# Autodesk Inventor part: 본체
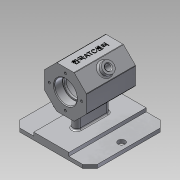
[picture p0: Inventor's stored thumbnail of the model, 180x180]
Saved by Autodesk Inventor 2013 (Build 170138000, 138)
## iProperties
Created: 2018-06
Part Number: 본체
Material: 알루미늄 6061
Document SubType Name: Modeling
Designer: default
Density: 2.71 g/cm^3
Mass: 553.88 g
Surface Area: 602.123 cm^2
Volume: 204.384 cm^3
Author: default
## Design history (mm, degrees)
sketch "스케치1"
  geometry: L1 (-55, -55)-(55, -55); L2 (55, -55)-(55, 55); L3 (55, 55)-(-55, 55); L4 (-55, 55)-(-55, -55); L5 (-55, -55)-(55, 55); L6 (55, -55)-(-55, 55); 1 further point
  constraints: 12 end point, 2 midpoint, 2 parallel, 2 perpendicular, 1 horizontal
  dimensions: "d0" = 110 distance of L2.end L3.end
extrude "돌출1" new body sketch "스케치1" distance "d2" = 5; taper "d3" = 0 deg
chamfer "모따기1" distance "d4" = 10; stored, may be unused: second distance "d5" = 2, angle "d6" = 45 deg
sketch "스케치2"
  geometry: L1 (55, -45)-(55, 45) reference; L2 (45, 55)-(-45, 55) reference; L3 (-55, -25)-(55, -25); L4 (55, -25)-(55, 25); L5 (55, 25)-(-55, 25); L6 (-55, 25)-(-55, -25); L7 (-55, -25)-(55, 25); L8 (55, -25)-(-55, 25); 1 further point
  constraints: 12 end point, 2 midpoint, 2 parallel, 1 horizontal, 1 perpendicular, 1 point on line
  dimensions: "d7" = 30 distance between parallel lines of L2 L5
extrude "돌출2" join sketch "스케치2" distance "d8" = 5; taper "d9" = 0 deg
sketch "스케치3" dims "d10" = 60
  geometry: L1 (25, 10)-(25, 5) reference; L2 (25, 5)-(55, 5) reference; L3 (55, 5)-(55, 0) reference; L4 (55, 0)-(-55, 0) reference; L5 (-55, 0)-(-55, 5) reference; L6 (-55, 5)-(-25, 5) reference; L7 (-25, 5)-(-25, 10) reference; L8 (-25, 10)-(25, 10) reference; L9 (12.426, 92)-(30, 74.426); L10 (30, 74.426)-(30, 49.574); L11 (30, 49.574)-(12.426, 32); L12 (12.426, 32)-(-12.426, 32); L13 (-12.426, 32)-(-30, 49.574); L14 (-30, 49.574)-(-30, 74.426); L15 (-30, 74.426)-(-12.426, 92); L16 (-12.426, 92)-(12.426, 92); 4 further points
  constraints: 16 end point, 2 vertical alignment, 1 coincident, 1 midpoint, 1 parallel, 19 other
  dimensions: "d12" = 62 vertical distance of L4.end point (0, 62)
extrude "돌출3" join sketch "스케치3" stored distance "d13" = 70; taper "d14" = 0 deg
sketch "스케치4"
  geometry: L1 (-55, 10)-(55, 10) reference; L2 (55, 10)-(55, 0) reference; L3 (55, 0)-(-55, 0) reference; L4 (-55, 0)-(-55, 10) reference; L5 (35, 92)-(35, 32) reference; L6 (35, 32)-(-35, 32) reference; L7 (-35, 32)-(-35, 92) reference; L8 (-35, 92)-(35, 92) reference; L9 (-35, 62)-(35, 62); L10 (35, 78)-(23, 78); L11 (23, 78)-(23, 76); L12 (23, 76)-(20, 76); L13 (20, 76)-(20, 87); L14 (20, 87)-(-20, 87); L15 (-20, 87)-(-20, 76); L16 (-20, 76)-(-23, 76); L17 (-23, 76)-(-23, 78); L18 (-23, 78)-(-35, 78); 3 further points
  constraints: 20 end point, 7 parallel, 4 midpoint, 2 horizontal alignment, 2 perpendicular, 2 point on line, 1 vertical alignment
  dimensions: "d15" = 50 diameter of L14 L9; "d17" = 28 diameter of L15.end L9; "d18" = 32 diameter of L17.end L9; "d19" = 12 distance of L17.end L18.end; "d20" = 40 distance of L13.end L14.end; "d21" = 12 distance of L10.start L10.end
revolve "회전1" sketch "스케치4" stored, may be unused: angle "d22" = 90 deg
sketch "스케치5"
  geometry: C1 r 16 at (-62, 0) reference; 2 further points
  constraints: 1 vertical alignment
  dimensions: "d23" = 23 distance of C1.centre point (-62, 23)
hole "구멍1" sketch "스케치5" at (-62, 23) diameter "d24" = 3.242; stored, may be unused: countersink angle "d28" = 90 deg, drill point angle "d30" = 118 deg; dims "d25" = 8, "d26" = 4, "d27" = 2, "d29" = 10
sketch "스케치6"
  geometry: L1 (-19, -5)-(19, -5); L2 (24, 0)-(24, 0); L3 (19, 5)-(-19, 5); L4 (-24, 0)-(-24, 0); L5 (-24, -5)-(24, 5); L6 (24, -5)-(-24, 5); A1 r 5 centre (-19, 0) between (-19, 5) and (-24, 0); A2 r 5 centre (-19, 0) between (-24, 0) and (-19, -5); A3 r 5 centre (19, 0) between (19, -5) and (24, 0); A4 r 5 centre (19, 0) between (24, 0) and (19, 5); 1 further point
  constraints: 12 end point, 8 point on circle, 8 point on line, 8 tangent, 4 centre point, 3 equal radius, 2 midpoint, 2 parallel, 1 coincident, 1 horizontal, 1 perpendicular
  dimensions: "d34" = 5 radius of A1; "d35" = 38 distance of A3.centre A1.centre
extrude "돌출4" join sketch "스케치6" stored distance "d36" = 70; taper "d37" = 0 deg
sketch "스케치7"
  geometry: L1 (-45, -55)-(45, -55) reference; 2 further points
  constraints: 1 vertical alignment
  dimensions: "d38" = 10 distance from line of L1 point (0, -45)
hole "구멍2" sketch "스케치7" at (0, -45) diameter "d39" = 10; stored, may be unused: countersink angle "d43" = 90 deg, drill point angle "d45" = 118 deg; dims "d40" = 8, "d41" = 4, "d42" = 2, "d44" = 10
node "작업 평면1"
sketch "스케치8"
  geometry: L1 (70, 0)-(0, 0) reference; L2 (70, 24.853)-(70, 0) reference; L3 (70, 24.853)-(0, 24.853) reference; L4 (0, 0)-(0, 24.853) reference; C1 r 8 at (35, 12.426); 2 further points
  constraints: 1 centre point, 1 horizontal alignment, 1 midpoint, 1 vertical alignment
  dimensions: "d47" = 16 diameter of C1
extrude "돌출5" join sketch "스케치8" stored distance "d49" = 70; taper "d50" = 0 deg
sketch "스케치9"
  geometry: C1 r 8 at (0, 0) reference; C2 r 4 at (0, 0); 1 further point
  constraints: 1 centre point, 1 coincident
  dimensions: "d51" = 8 diameter of C2
extrude "돌출6" cut sketch "스케치9" stored distance "d53" = 70; taper "d54" = 0 deg
fillet "모깎기1" dims "d55" = 1
node "작업 평면2"
sketch "스케치10"
  geometry: L1 (0, -24.024)-(0, 0) reference; L2 (0, 17.695)-(70, 17.695) reference; 2 further points
  constraints: 1 other
  dimensions: "d57" = 35 distance from line of L1 point (35, -12.305); "d58" = 30 distance from line of L2 point (35, -12.305)
feature "엠보싱1" sketch "스케치10" dims "d0" = 110, "d59" = 0.5, "d60" = 0
fillet "모깎기2" dims "d61" = 0.3
fillet "모깎기3" dims "d62" = 3
chamfer "모따기2" distance "d63" = 1; stored, may be unused: second distance "d64" = 2, angle "d65" = 45 deg
fillet "모깎기4" dims "d66" = 2
node "솔리드1"
pattern_circular "원형 패턴1" dims angle "d32" = 360 deg
mirror "대칭1"
mirror "대칭2"
node "투영된 루프1"
node "절단 모서리 투영1"
node "절단 모서리 투영2"
other parameters: "d46" = 7
